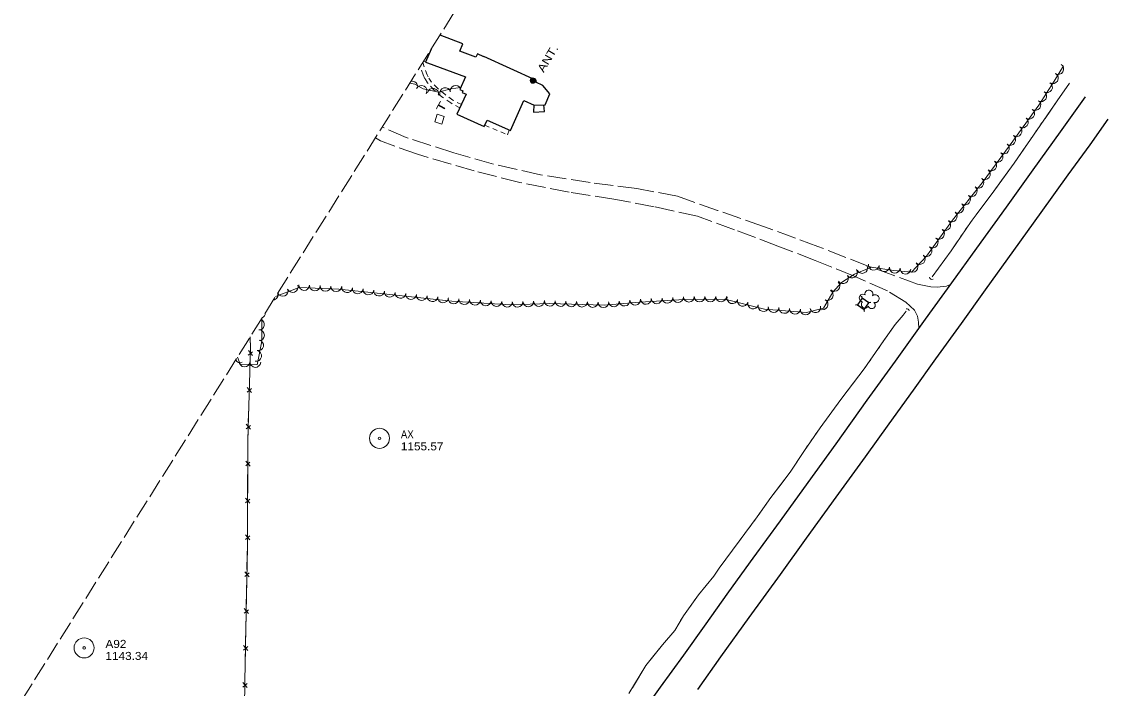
# Model space of a CAD drawing. Extents: x 298072 to 300359, y 47756 to 50122.
# Drawn here: x 298855 to 299670, y 48824 to 49323 of the extents above; entities that cross this region are included whole.
import ezdxf

# ---------------------------------------------------------------- set-up
doc = ezdxf.new("R2010")
doc.units = 0
doc.header["$LTSCALE"] = 2.4
doc.linetypes.add('LONG_DASHED', pattern=[7.5, 6, -1.5])
doc.linetypes.add('SHORT_DASHED', pattern=[2.7, 1.5, -1.2])
for name, color, linetype, lineweight in [('11', 7, 'Continuous', 25), ('12', 7, 'Continuous', 25), ('14', 7, 'Continuous', 13), ('15', 7, 'Continuous', 13), ('17', 7, 'LONG_DASHED', 13), ('18', 7, 'Continuous', 13), ('19', 7, 'Continuous', 13), ('21', 7, 'Continuous', 25), ('4', 7, 'Continuous', 13), ('6', 7, 'Continuous', 13)]:
    doc.layers.add(name, color=color, linetype=linetype, lineweight=lineweight)

msp = doc.modelspace()

# ---------------------------------------------------------------- linework, layer by layer
at = {"layer": '11'}
for points in [[(299315.556, 48798.256), (299334.267, 48824.557), (299351.787, 48848.593), (299367.194, 48870.243), (299385.627, 48895.906), (299403.872, 48921.117), (299424.324, 48949.261), (299445.075, 48977.895), (299465.894, 49006.877), (299489.257, 49039.581), (299510.579, 49068.904), (299532.854, 49100.174), (299552.731, 49127.597), (299571.375, 49153.431), (299593.618, 49184.233), (299613.682, 49212.197), (299634.111, 49240.708), (299652.953, 49266.87)], [(299362.207, 48822.854), (299379.626, 48847.266), (299400.78, 48876.62), (299424.163, 48908.843), (299443.654, 48936.17), (299465.932, 48966.886), (299487.902, 48997.191), (299505.69, 49021.932), (299523.861, 49047.119), (299540.766, 49070.585), (299559.924, 49097.119), (299578.024, 49122.293), (299599.165, 49151.691), (299619.667, 49180.229), (299639.98, 49208.374), (299656.282, 49231.041), (299669.962, 49250.066)]]:
    msp.add_lwpolyline(points, dxfattribs=at)
at = {"layer": '12'}
msp.add_lwpolyline([(299162.438, 49302.721), (299158.022, 49292.943), (299159.691, 49292.524), (299188.008, 49281.923), (299183.984, 49272.32), (299186.09, 49271.369), (299185.576, 49270.23), (299188.526, 49268.898), (299181.739, 49253.868), (299202.197, 49244.63), (299204.42, 49249.554), (299221.774, 49241.718), (299231.892, 49264.126), (299239.48, 49260.7), (299247.752, 49261.017), (299251.336, 49269.229), (299246.186, 49275.472), (299240.802, 49278.026), (299241.415, 49279.207), (299201.849, 49297.073), (299201.777, 49296.914), (299196.985, 49299.078), (299195.839, 49296.539), (299183.825, 49301.165), (299186.111, 49306.761), (299169.056, 49313.242)], dxfattribs=at)
at = {"layer": '12', "linetype": 'LONG_DASHED'}
msp.add_lwpolyline([(299239.242, 49260.808), (299239.195, 49255.366), (299247.279, 49255.925), (299246.943, 49260.986)], dxfattribs=at)
at = {"layer": '12', "lineweight": 13}
msp.add_lwpolyline([(299170.404, 49246.553), (299172.132, 49252.205), (299166.881, 49253.81), (299165.153, 49248.158)], close=True, dxfattribs=at)
at = {"layer": '14'}
for centre, radius in [((299238.644, 49279.126), 2.018), ((299238.632, 49279.131), 1.518), ((299238.668, 49279.113), 1.008), ((299238.662, 49279.122), 0.502)]:
    msp.add_circle(centre, radius, dxfattribs=at)
at = {"layer": '15'}
for p, q in [((299026.872, 49078.4), (299026.812, 49087.143)), ((299025.255, 49073.236), (299028.479, 49075.917)), ((299028.461, 49072.975), (299025.357, 49076.752)), ((299026.419, 49062.004), (299026.704, 49071.874)), ((299026.095, 49050.781), (299026.419, 49062.004)), ((299024.457, 49045.617), (299027.681, 49048.298)), ((299027.664, 49045.356), (299024.559, 49049.133)), ((299025.621, 49034.385), (299025.906, 49044.256)), ((299025.297, 49023.162), (299025.621, 49034.385)), ((299023.66, 49017.998), (299026.883, 49020.679)), ((299026.866, 49017.737), (299023.761, 49021.514)), ((299024.861, 48995.537), (299024.9, 49006.765)), ((299026.567, 48990.154), (299023.367, 48993.851)), ((299023.355, 48990.333), (299026.51, 48993.095)), ((299024.803, 48979.134), (299024.838, 48989.009)), ((299024.764, 48967.907), (299024.803, 48979.134)), ((299023.258, 48962.703), (299026.413, 48965.465)), ((299026.47, 48962.523), (299023.27, 48966.221)), ((299024.707, 48951.504), (299024.741, 48961.379)), ((299024.667, 48940.276), (299024.707, 48951.504)), ((299023.161, 48935.073), (299026.316, 48937.835)), ((299026.373, 48934.893), (299023.174, 48938.591)), ((299024.299, 48912.649), (299024.52, 48923.875)), ((299022.709, 48907.471), (299025.908, 48910.181)), ((299025.918, 48907.239), (299022.778, 48910.988)), ((299023.976, 48896.25), (299024.171, 48906.123)), ((299023.755, 48885.024), (299023.976, 48896.25)), ((299022.165, 48879.846), (299025.364, 48882.556)), ((299025.374, 48879.614), (299022.235, 48883.363)), ((299023.432, 48868.625), (299023.627, 48878.498)), ((299023.211, 48857.399), (299023.432, 48868.625)), ((299021.622, 48852.221), (299024.82, 48854.931)), ((299024.83, 48851.989), (299021.691, 48855.738)), ((299022.751, 48829.773), (299022.904, 48840.999)), ((299021.192, 48824.585), (299024.374, 48827.314)), ((299024.402, 48824.372), (299021.24, 48828.102))]:
    msp.add_line(p, q, dxfattribs=at)
for points in [[(299017.262, 48537.143), (299020.447, 48615.518), (299020.97, 48684.962), (299021.815, 48761.361), (299022.94, 48843.61), (299024.629, 48929.407), (299024.911, 49009.798), (299026.876, 49077.821), (299026.812, 49087.143)], [(299024.9, 49006.765), (299024.911, 49009.798), (299025.109, 49016.637)], [(299024.52, 48923.875), (299024.629, 48929.407), (299024.644, 48933.749)], [(299022.904, 48840.999), (299022.94, 48843.61), (299023.083, 48850.872)]]:
    msp.add_lwpolyline(points, dxfattribs=at)
for centre, radius, start, end in [((299537.807, 49132.034), 1.978, 187.48715, 293.72672), ((299519.009, 49106.409), 1.738, 4.63589, 110.87545)]:
    msp.add_arc(centre, radius, start, end, dxfattribs=at)
at = {"layer": '17'}
msp.add_line((299158.094, 49293.103), (299156.663, 49293.542), dxfattribs=at)
at = {"layer": '17', "linetype": 'SHORT_DASHED'}
for points in [[(299183.887, 49258.625), (299177.039, 49262.4), (299170.471, 49266.961), (299164.337, 49272.106), (299159.686, 49277.373), (299157.732, 49280.516), (299156.327, 49283.362), (299154.302, 49289.79)], [(299185.024, 49261.142), (299178.564, 49264.46), (299172.776, 49268.604), (299167.156, 49273.358), (299162.627, 49277.892), (299160.114, 49281.887), (299159.449, 49283.355), (299156.093, 49292.637)], [(299202.627, 49245.583), (299219.561, 49238.523), (299221.018, 49242.06)]]:
    msp.add_lwpolyline(points, dxfattribs=at)
at = {"layer": '17'}
for points in [[(299551.692, 49126.164), (299548.636, 49124.994), (299541.637, 49124.2), (299536.83, 49124.606), (299526.866, 49126.588), (299490.071, 49140.11), (299452.289, 49154.785), (299411.524, 49169.816), (299377.097, 49181.822), (299347.054, 49192.398), (299316.605, 49198.25), (299281.478, 49202.705), (299244.3, 49208.516), (299209.065, 49216.55), (299179.255, 49224.885), (299143.609, 49236.496), (299125.724, 49244.364)], [(299528.038, 49093.413), (299527.626, 49098.054), (299526.829, 49102.482), (299524.719, 49106.974), (299518.198, 49113.106), (299504.431, 49121.567), (299479.359, 49132.59), (299450.321, 49144.269), (299422.346, 49155.123), (299389.677, 49167.318), (299362.046, 49177.496), (299329.434, 49184.593), (299299.429, 49190.3), (299265.713, 49195.528), (299228.897, 49202.721), (299194.63, 49211.366), (299152.046, 49223.84), (299124.301, 49233.875), (299120.575, 49236.181)]]:
    msp.add_lwpolyline(points, dxfattribs=at)
at = {"layer": '18'}
for points in [[(299045.702, 49117.168), (299063.372, 49123.927), (299093.208, 49122.793), (299124.336, 49119.448), (299177.754, 49113.801), (299221.824, 49111.074), (299251.024, 49112.011), (299292.128, 49110.83), (299318.833, 49113.071), (299352.266, 49115.033), (299382.415, 49115.291), (299412.339, 49107.679), (299443.637, 49105.388), (299456.571, 49108.478), (299463.389, 49120.609), (299469.906, 49127.663), (299479.662, 49133.931), (299492.398, 49139.181), (299509.118, 49136.807), (299522.472, 49135.619), (299533.578, 49147.605), (299553.129, 49174.548), (299575.31, 49202.526), (299596.383, 49230.974), (299617.84, 49260.609), (299629.515, 49278.652), (299636.402, 49290.101)], [(299184.684, 49273.885), (299177.086, 49272.9), (299167.814, 49270.442), (299156.3, 49272.98), (299150.006, 49276.333), (299146.321, 49277.104)], [(299017.114, 49071.728), (299019.085, 49066.6), (299032.022, 49065.999), (299035.442, 49083.786), (299035.367, 49100.742)]]:
    msp.add_lwpolyline(points, dxfattribs=at)
for centre, radius, start, end in [((299632.528, 49287.742), 4.019, 238.97919, 58.96386), ((299148.085, 49274.496), 4.187, 348.19419, 101.31418), ((299628.386, 49280.855), 4.019, 238.97919, 58.96386), ((299155.038, 49271.169), 4.187, 331.96211, 151.94679), ((299163.749, 49269.094), 4.187, 347.57689, 167.56157), ((299172.912, 49269.526), 4.187, 14.8552, 194.83988), ((299180.813, 49271.173), 4.187, 30.92538, 187.37893), ((299180.813, 49271.173), 4.187, 7.39425, 9.8376), ((299619.726, 49267.396), 4.019, 237.10216, 57.08683), ((299624.092, 49274.143), 4.019, 237.10216, 57.08683), ((299615.365, 49260.778), 4.019, 234.10152, 54.0862), ((299610.652, 49254.268), 4.019, 234.10152, 54.0862), ((299605.939, 49247.758), 4.019, 234.10152, 54.0862), ((299596.512, 49234.739), 4.019, 234.10152, 54.0862), ((299601.225, 49241.248), 4.019, 234.10152, 54.0862), ((299591.769, 49228.279), 4.019, 233.47828, 53.46296), ((299586.985, 49221.821), 4.019, 233.47828, 53.46296), ((299582.201, 49215.363), 4.019, 233.47828, 53.46296), ((299572.632, 49202.534), 4.019, 231.60023, 51.58491), ((299577.417, 49208.904), 4.019, 233.47828, 53.46296), ((299567.639, 49196.236), 4.019, 231.60023, 51.58491), ((299562.646, 49189.938), 4.019, 231.60023, 51.58491), ((299557.653, 49183.64), 4.019, 231.60023, 51.58491), ((299547.821, 49170.815), 4.019, 234.04141, 54.02609), ((299552.66, 49177.342), 4.019, 231.60023, 51.58491), ((299543.101, 49164.31), 4.019, 234.04141, 54.02609), ((299538.381, 49157.805), 4.019, 234.04141, 54.02609), ((299528.638, 49145.369), 4.019, 227.19006, 47.17474), ((299533.661, 49151.3), 4.019, 234.04141, 54.02609), ((299485.508, 49138.616), 4.019, 202.40997, 22.39464), ((299494.131, 49141.059), 4.019, 171.9265, 351.91118), ((299502.089, 49139.93), 4.019, 171.9265, 351.91118), ((299523.176, 49139.474), 4.019, 227.19006, 47.17474), ((299471.051, 49130.899), 4.019, 212.72745, 32.71213), ((299477.813, 49135.243), 4.019, 212.72745, 32.71213), ((299509.94, 49138.846), 4.019, 174.92389, 354.90857), ((299517.946, 49138.133), 4.019, 174.92389, 354.90857), ((299058.546, 49124.333), 4.019, 200.93873, 20.92341), ((299067.123, 49125.889), 4.019, 177.83103, 357.8157), ((299075.155, 49125.584), 4.019, 177.83103, 357.8157), ((299083.186, 49125.279), 4.019, 177.83103, 357.8157), ((299091.217, 49124.974), 4.019, 177.83103, 357.8157), ((299099.363, 49124.247), 4.019, 173.87422, 353.8589), ((299107.354, 49123.388), 4.019, 173.87422, 353.8589), ((299464.748, 49125.18), 4.019, 227.27366, 47.25833), ((299043.532, 49118.591), 4.019, 278.01418, 17.63577), ((299051.039, 49121.462), 4.019, 204.10003, 20.92341), ((299115.345, 49122.53), 4.019, 173.87422, 353.8589), ((299123.336, 49121.671), 4.019, 173.87422, 353.8589), ((299131.325, 49120.824), 4.019, 173.97314, 353.95782), ((299139.317, 49119.979), 4.019, 173.97314, 353.95782), ((299147.31, 49119.135), 4.019, 173.97314, 353.95782), ((299155.302, 49118.29), 4.019, 173.97314, 353.95782), ((299163.295, 49117.445), 4.019, 173.97314, 353.95782), ((299171.287, 49116.6), 4.019, 173.97314, 353.95782), ((299179.193, 49115.819), 4.019, 176.46678, 356.45146), ((299187.215, 49115.323), 4.019, 176.46678, 356.45146), ((299323.391, 49115.446), 4.019, 183.36619, 3.35086), ((299331.414, 49115.916), 4.019, 183.36619, 3.35086), ((299339.437, 49116.387), 4.019, 183.36619, 3.35086), ((299347.461, 49116.858), 4.019, 183.36619, 3.35086), ((299355.595, 49117.165), 4.019, 180.49796, 0.48264), ((299363.631, 49117.234), 4.019, 180.49796, 0.48264), ((299371.668, 49117.303), 4.019, 180.49796, 0.48264), ((299379.705, 49117.371), 4.019, 180.49796, 0.48264), ((299388.113, 49116.012), 4.019, 165.73559, 345.72027), ((299459.714, 49118.364), 4.019, 240.67032, 60.655), ((299486.08, 49116.14), 2.777, 55.8556, 263.62859), ((299490.523, 49119.164), 2.974, 332.88471, 194.11859), ((299495.221, 49115.671), 2.975, 250.53553, 133.5088), ((299195.237, 49114.827), 4.019, 176.46678, 356.45146), ((299203.258, 49114.33), 4.019, 176.46678, 356.45146), ((299211.28, 49113.834), 4.019, 176.46678, 356.45146), ((299219.302, 49113.338), 4.019, 176.46678, 356.45146), ((299227.134, 49113.349), 4.019, 181.8456, 1.83027), ((299235.166, 49113.607), 4.019, 181.8456, 1.83027), ((299243.199, 49113.864), 4.019, 181.8456, 1.83027), ((299251.36, 49114.106), 4.019, 178.36189, 358.34657), ((299259.394, 49113.875), 4.019, 178.36189, 358.34657), ((299267.428, 49113.644), 4.019, 178.36189, 358.34657), ((299275.461, 49113.413), 4.019, 178.36189, 358.34657), ((299283.495, 49113.182), 4.019, 178.36189, 358.34657), ((299291.529, 49112.952), 4.019, 178.36189, 358.34657), ((299299.303, 49113.543), 4.019, 184.80451, 4.78918), ((299307.312, 49114.215), 4.019, 184.80451, 4.78918), ((299315.321, 49114.887), 4.019, 184.80451, 4.78918), ((299395.902, 49114.031), 4.019, 165.73559, 345.72027), ((299403.691, 49112.049), 4.019, 165.73559, 345.72027), ((299411.48, 49110.068), 4.019, 165.73559, 345.72027), ((299419.091, 49109.294), 4.019, 175.8211, 355.80578), ((299427.106, 49108.707), 4.019, 175.8211, 355.80578), ((299435.122, 49108.12), 4.019, 175.8211, 355.80578), ((299443.137, 49107.534), 4.019, 175.8211, 355.80578), ((299450.328, 49109.149), 4.019, 193.44407, 13.42875), ((299455.777, 49111.358), 4.019, 240.67032, 60.655), ((299487.653, 49111.329), 2.783, 132.53262, 333.54366), ((299492.664, 49110.776), 2.611, 195.24076, 53.17337), ((299033.284, 49096.264), 4.019, 270.26008, 66.71087), ((299033.994, 49104.95), 4.019, 295.67411, 359.97585), ((299033.319, 49088.227), 4.019, 270.26008, 90.24476), ((299032.699, 49080.661), 4.019, 259.12393, 79.10861), ((299031.182, 49072.769), 4.019, 259.12393, 79.10861), ((299019.373, 49071.715), 4.019, 209.3033, 291.01574), ((299022.545, 49068.545), 4.019, 177.34785, 357.33253), ((299030.573, 49068.172), 4.019, 177.34785, 357.33253)]:
    msp.add_arc(centre, radius, start, end, dxfattribs=at)
at = {"layer": '19'}
for p, q in [((299618.717, 49245.273), (299619.989, 49247.1)), ((299614.904, 49239.789), (299616.172, 49241.618)), ((299611.098, 49234.301), (299612.367, 49236.13)), ((299563.038, 49167.414), (299564.296, 49169.251)), ((299559.263, 49161.903), (299560.521, 49163.74)), ((299494.16, 49073.348), (299495.305, 49074.989)), ((299497.593, 49078.272), (299498.737, 49079.913)), ((299490.728, 49068.424), (299491.872, 49070.066)), ((299446.876, 49008.752), (299448.015, 49010.398)), ((299450.291, 49013.692), (299451.43, 49015.338)), ((299443.461, 49003.812), (299444.6, 49005.458)), ((299400.469, 48943.544), (299401.653, 48945.16)), ((299404.019, 48948.39), (299405.203, 48950.005)), ((299396.919, 48938.699), (299398.102, 48940.314)), ((299352.546, 48879.44), (299353.716, 48881.065)), ((299356.056, 48884.315), (299357.226, 48885.939)), ((299349.368, 48874.35), (299350.379, 48876.078))]:
    msp.add_line(p, q, dxfattribs=at)
for points in [[(299537.949, 49131.979), (299552.203, 49151.594), (299567.167, 49173.443), (299582.907, 49194.391), (299599.313, 49217.305), (299616.568, 49242.189), (299631.758, 49263.994), (299641.013, 49277.236)], [(299622.535, 49250.754), (299631.758, 49263.994), (299641.013, 49277.236)], [(299589.97, 49204.256), (299599.313, 49217.305), (299608.562, 49230.643)], [(299570.803, 49178.281), (299582.907, 49194.391), (299589.97, 49204.256)], [(299566.812, 49172.925), (299567.167, 49173.443), (299568.127, 49174.721)], [(299537.949, 49131.979), (299552.203, 49151.594), (299556.747, 49158.229)], [(299310.613, 48819.841), (299323.396, 48840.828), (299335.724, 48856.228), (299345.02, 48866.908), (299351.468, 48877.943), (299362.759, 48893.622), (299374.212, 48907.728), (299378.38, 48913.654), (299393.376, 48933.863), (299406.69, 48952.035), (299417.04, 48966.634), (299431.602, 48985.612), (299442.202, 49001.99), (299453.912, 49018.929), (299469.462, 49040.21), (299486.933, 49062.981), (299500.057, 49081.806), (299510.223, 49096.315), (299516.234, 49103.402), (299518.57, 49106.271)], [(299501.029, 49083.194), (299510.223, 49096.315), (299516.234, 49103.402), (299518.57, 49106.271)], [(299470.869, 49042.044), (299486.933, 49062.981), (299488.439, 49065.142)], [(299453.706, 49018.632), (299453.912, 49018.929), (299469.462, 49040.21), (299470.869, 49042.044)], [(299424.717, 48976.639), (299431.602, 48985.612), (299441.23, 49000.488)], [(299407.55, 48953.248), (299417.04, 48966.634), (299424.717, 48976.639)], [(299377.306, 48912.126), (299378.38, 48913.654), (299393.376, 48933.863), (299394.552, 48935.468)], [(299359.567, 48889.189), (299362.759, 48893.622), (299374.212, 48907.728), (299377.306, 48912.126)], [(299329.314, 48848.221), (299335.724, 48856.228), (299345.02, 48866.908), (299347.348, 48870.892)], [(299313.221, 48824.123), (299323.396, 48840.828), (299329.314, 48848.221)]]:
    msp.add_lwpolyline(points, dxfattribs=at)
at = {"layer": '21'}
for p, q in [((299485.491, 49115.997), (299485.245, 49117.476)), ((299482.003, 49111.114), (299480.525, 49110.869)), ((299487.132, 49106.148), (299486.885, 49107.627)), ((299491.853, 49112.756), (299490.373, 49112.511))]:
    msp.add_line(p, q, dxfattribs=at)
msp.add_lwpolyline([(299486.885, 49107.627), (299490.373, 49112.511), (299485.491, 49115.997), (299482.003, 49111.114)], close=True, dxfattribs=at)
at = {"layer": '4', "linetype": 'LONG_DASHED'}
msp.add_line((299332.839, 49573.576), (298725.651, 48608.445), dxfattribs=at)
at = {"layer": '6'}
for centre, radius in [((299123.664, 49010.994), 7.5), ((299123.664, 49010.994), 0.96), ((298902.204, 48853.925), 7.5), ((298902.204, 48853.925), 0.96)]:
    msp.add_circle(centre, radius, dxfattribs=at)

# ---------------------------------------------------------------- texts
at = {"layer": '12', "width": 1.5}
msp.add_text('T', height=6, rotation=61.073, dxfattribs=at).set_placement((299170.98, 49254.801))
at = {"layer": '14', "width": 1.2}
msp.add_text('ANT.', height=6, rotation=59.073, dxfattribs=at).set_placement((299246.696, 49284.705))
at = {"layer": '6'}
for s, width, p in [('AX', 0.9, (299139.664, 49010.994)), ('1155.57', 1.1, (299139.664, 49001.994)), ('A92', 1.1, (298918.204, 48853.925)), ('1143.34', 1.1, (298918.204, 48844.925))]:
    msp.add_text(s, height=6, dxfattribs=dict(at, width=width)).set_placement(p)

doc.saveas('drawing.dxf')
